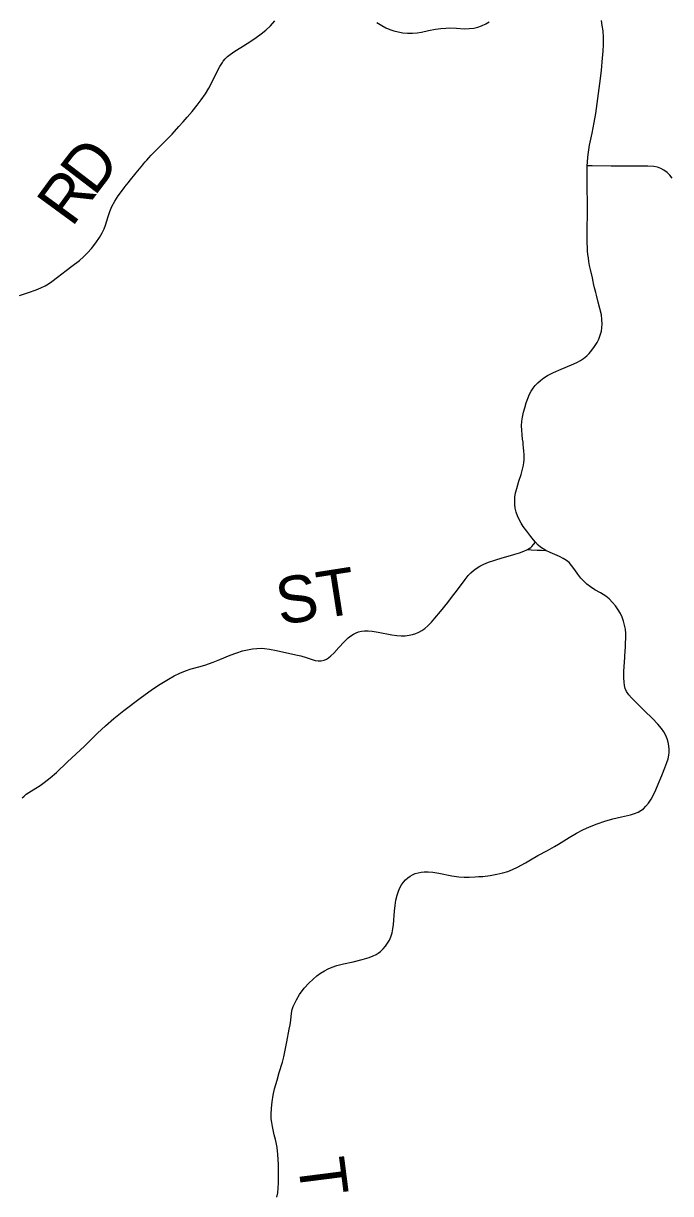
# Model space of a CAD drawing. Extents: x 0 to 34, y 0 to 22.
# Drawn here: x 5.245 to 6.032, y 14.51 to 15.933 of the extents above; entities that cross this region are included whole.
import ezdxf

# ---------------------------------------------------------------- set-up
doc = ezdxf.new("R2010")
doc.units = 0
doc.layers.add('GM_X_Township_Road', color=7, linetype='Continuous')
doc.layers.add('GM_X_Township_Road_Text', color=7, linetype='Continuous')

msp = doc.modelspace()

# ---------------------------------------------------------------- linework, layer by layer
at = {"layer": 'GM_X_Township_Road'}
for points in [[(5.2404, 15.6019), (5.251, 15.6055), (5.2603, 15.6088), (5.2661, 15.6112), (5.2716, 15.6139), (5.2754, 15.6161), (5.2795, 15.6189), (5.2864, 15.6242), (5.2971, 15.6326), (5.304, 15.6378), (5.313, 15.6445), (5.3182, 15.649), (5.323, 15.6538), (5.3279, 15.6594), (5.3332, 15.6662), (5.3374, 15.6724), (5.3409, 15.6783), (5.3432, 15.6833), (5.3447, 15.6874), (5.3464, 15.6927), (5.348, 15.6981), (5.3499, 15.704), (5.3527, 15.7102), (5.3562, 15.7168), (5.3603, 15.7232), (5.3641, 15.7285), (5.3675, 15.7329), (5.3701, 15.7362), (5.3727, 15.7395), (5.3735, 15.7405), (5.382, 15.7511), (5.3901, 15.7611), (5.391, 15.762), (5.3929, 15.7644), (5.3941, 15.7658), (5.3949, 15.7667), (5.3974, 15.7694), (5.4004, 15.7726), (5.417, 15.7893), (5.4257, 15.7983), (5.434, 15.8074), (5.4394, 15.8134), (5.4442, 15.819), (5.4502, 15.826), (5.4564, 15.8335), (5.4612, 15.8398), (5.4663, 15.8474), (5.4703, 15.8541), (5.4758, 15.8643), (5.4812, 15.8753), (5.484, 15.8807), (5.4869, 15.8852), (5.488, 15.887), (5.4903, 15.8898), (5.493, 15.8925), (5.4963, 15.8952), (5.5019, 15.8992), (5.5093, 15.9038), (5.5204, 15.9106), (5.5282, 15.9157), (5.5342, 15.9201), (5.5399, 15.9249), (5.5453, 15.9301), (5.5507, 15.936)], [(5.6749, 15.9339), (5.6807, 15.9303), (5.6857, 15.9277), (5.6908, 15.9254), (5.6955, 15.9238), (5.7009, 15.9225), (5.7064, 15.9216), (5.712, 15.9211), (5.7182, 15.9211), (5.7238, 15.9216), (5.7293, 15.9224), (5.7378, 15.9242), (5.7463, 15.926), (5.7525, 15.9269), (5.7587, 15.9273), (5.7636, 15.9274), (5.7717, 15.927), (5.781, 15.9265), (5.7872, 15.9266), (5.7928, 15.9272), (5.7976, 15.9282), (5.8022, 15.9299), (5.8074, 15.9323), (5.8114, 15.9349)], [(5.9308, 15.7596), (5.9309, 15.7641), (5.9313, 15.7703), (5.9321, 15.7764), (5.9335, 15.785), (5.9365, 15.7996), (5.9393, 15.8123), (5.9412, 15.8233), (5.946, 15.8597), (5.9479, 15.8757), (5.9494, 15.8912), (5.95, 15.8986), (5.9504, 15.9078), (5.9503, 15.9158), (5.9499, 15.9238), (5.949, 15.9304), (5.9479, 15.9365)], [(5.8678, 15.302), (5.8652, 15.3051), (5.8621, 15.309), (5.8571, 15.3155), (5.8528, 15.3212), (5.8503, 15.3252), (5.8478, 15.3295), (5.8458, 15.334), (5.8442, 15.3387), (5.8431, 15.3435), (5.8426, 15.3478), (5.8425, 15.3521), (5.8428, 15.357), (5.8436, 15.3619), (5.845, 15.3673), (5.8477, 15.3762), (5.8504, 15.3845), (5.8525, 15.3923), (5.8532, 15.3959), (5.8537, 15.3989), (5.8539, 15.402), (5.854, 15.4082), (5.8535, 15.4131), (5.8532, 15.417), (5.8528, 15.4209), (5.8526, 15.4237), (5.8521, 15.4274), (5.8516, 15.4328), (5.8511, 15.4382), (5.8509, 15.4436), (5.8513, 15.4493), (5.8521, 15.4541), (5.8532, 15.4603), (5.8547, 15.4656), (5.8564, 15.4714), (5.8583, 15.4768), (5.8605, 15.4819), (5.8625, 15.4858), (5.8648, 15.4894), (5.8675, 15.4928), (5.8705, 15.496), (5.8738, 15.4988), (5.8778, 15.5018), (5.8825, 15.5047), (5.8897, 15.5083), (5.8988, 15.5124), (5.9114, 15.5176), (5.9182, 15.5207), (5.9225, 15.5231), (5.9262, 15.5256), (5.93, 15.5287), (5.9331, 15.5317), (5.9364, 15.5355), (5.9397, 15.54), (5.9426, 15.5447), (5.9448, 15.5491), (5.9466, 15.5538), (5.9479, 15.5586), (5.9485, 15.5629), (5.9487, 15.5678), (5.9485, 15.5728), (5.9479, 15.5784), (5.9461, 15.5864), (5.9441, 15.594), (5.9418, 15.6023), (5.941, 15.6059), (5.9396, 15.6114), (5.9385, 15.6168), (5.9379, 15.6192), (5.9369, 15.6235), (5.9345, 15.6338), (5.9336, 15.6386), (5.9328, 15.6436), (5.9321, 15.6479), (5.9316, 15.6518), (5.9312, 15.6563), (5.9311, 15.66), (5.9308, 15.6659), (5.9305, 15.6708), (5.9306, 15.6745), (5.9306, 15.6801), (5.9307, 15.6838), (5.9307, 15.6868), (5.9308, 15.6899), (5.9309, 15.6948), (5.9309, 15.6991), (5.9309, 15.7066), (5.9309, 15.7129), (5.9309, 15.7203), (5.9307, 15.7271), (5.9305, 15.7362), (5.9305, 15.7461), (5.9307, 15.7559), (5.9308, 15.7596)], [(6.0341, 15.7446), (6.0311, 15.7485), (6.028, 15.7516), (6.024, 15.7545), (6.0202, 15.7565), (6.0161, 15.758), (6.0118, 15.7589), (6.0044, 15.7594), (5.9833, 15.7592), (5.9597, 15.7594), (5.9367, 15.7596), (5.9308, 15.7596)], [(5.8581, 15.2932), (5.8599, 15.2942), (5.8619, 15.2956), (5.8632, 15.2969), (5.8653, 15.2993), (5.8678, 15.302)], [(5.8804, 15.292), (5.877, 15.2939), (5.874, 15.2961), (5.8712, 15.2984), (5.8678, 15.302)], [(5.2435, 14.9911), (5.2457, 14.9933), (5.2485, 14.9957), (5.2516, 14.9978), (5.2602, 15.0028), (5.2653, 15.0062), (5.2703, 15.0099), (5.2776, 15.0157), (5.2851, 15.0222), (5.2983, 15.0344), (5.3195, 15.0545), (5.335, 15.0698), (5.3446, 15.0787), (5.355, 15.0875), (5.3671, 15.0972), (5.387, 15.1122), (5.402, 15.1232), (5.4113, 15.1294), (5.4213, 15.1356), (5.4284, 15.1395), (5.4351, 15.1427), (5.442, 15.1455), (5.449, 15.1479), (5.4598, 15.151), (5.4669, 15.1531), (5.4699, 15.154), (5.4757, 15.1562), (5.4838, 15.1594), (5.4964, 15.1647), (5.5045, 15.1677), (5.5116, 15.1699), (5.5175, 15.1713), (5.5235, 15.1724), (5.529, 15.1729), (5.5345, 15.1731), (5.5381, 15.1729), (5.5442, 15.172), (5.5526, 15.1703), (5.5762, 15.1651), (5.5822, 15.1638), (5.5887, 15.1618), (5.5963, 15.1593), (5.5998, 15.1584), (5.6035, 15.1578), (5.6071, 15.1577), (5.6106, 15.1586), (5.6134, 15.1599), (5.616, 15.1615), (5.6188, 15.1638), (5.6224, 15.1672), (5.6287, 15.174), (5.635, 15.1808), (5.6398, 15.1856), (5.6432, 15.1884), (5.6463, 15.1904), (5.6496, 15.192), (5.6526, 15.193), (5.6562, 15.1939), (5.6599, 15.1943), (5.6642, 15.1944), (5.6691, 15.1939), (5.6764, 15.1927), (5.6932, 15.1893), (5.6993, 15.1885), (5.7042, 15.1882), (5.7091, 15.1882), (5.714, 15.1889), (5.7183, 15.1898), (5.7224, 15.1912), (5.7258, 15.1927), (5.7296, 15.1948), (5.7332, 15.1973), (5.737, 15.2004), (5.7414, 15.2048), (5.7455, 15.2095), (5.7522, 15.2176), (5.7611, 15.2287), (5.7682, 15.238), (5.7704, 15.2409), (5.7821, 15.2569), (5.786, 15.2617), (5.789, 15.2648), (5.7923, 15.2677), (5.7958, 15.2702), (5.8, 15.2728), (5.805, 15.2753), (5.8107, 15.2777), (5.8183, 15.2804), (5.8272, 15.2831), (5.8403, 15.2867), (5.8426, 15.2875), (5.8485, 15.2893), (5.8537, 15.2912), (5.8572, 15.2927), (5.8581, 15.2932)], [(5.7984, 14.8954), (5.8036, 14.8956), (5.8125, 14.8968), (5.8208, 14.8982), (5.8281, 14.8999), (5.834, 14.9018), (5.8397, 14.904), (5.8459, 14.907), (5.8557, 14.9123), (5.8617, 14.9157), (5.8708, 14.921), (5.8822, 14.9273), (5.8908, 14.9322), (5.8956, 14.935), (5.9087, 14.9431), (5.9178, 14.9483), (5.9255, 14.9522), (5.9334, 14.9558), (5.9426, 14.9595), (5.952, 14.9628), (5.962, 14.9658), (5.9725, 14.9682), (5.9833, 14.9706), (5.9882, 14.972), (5.9927, 14.9739), (5.996, 14.9757), (5.999, 14.9779), (6.002, 14.9809), (6.0052, 14.9848), (6.0084, 14.9894), (6.0105, 14.9932), (6.014, 15.0011), (6.0168, 15.008), (6.0214, 15.0182), (6.0252, 15.0278), (6.0276, 15.0343), (6.029, 15.0385), (6.03, 15.043), (6.0304, 15.0464), (6.0304, 15.0501), (6.03, 15.0544), (6.0292, 15.0587), (6.028, 15.0629), (6.0263, 15.0669), (6.024, 15.0713), (6.0211, 15.0755), (6.0166, 15.0806), (6.0101, 15.0875), (6.0004, 15.0971), (5.9903, 15.1072), (5.9846, 15.1128), (5.9812, 15.1166), (5.9785, 15.1205), (5.9768, 15.1241), (5.9759, 15.128), (5.9756, 15.1318), (5.9752, 15.1373), (5.9754, 15.1448), (5.9764, 15.1624), (5.9769, 15.1706), (5.9771, 15.1737), (5.9774, 15.1793), (5.9776, 15.1853), (5.9776, 15.191), (5.9771, 15.1965), (5.9762, 15.2013), (5.9749, 15.206), (5.9732, 15.2107), (5.9711, 15.2152), (5.9683, 15.22), (5.9651, 15.2246), (5.9615, 15.2289), (5.9572, 15.2333), (5.9533, 15.2365), (5.947, 15.2404), (5.94, 15.2442), (5.9345, 15.2476), (5.9302, 15.251), (5.9263, 15.2549), (5.923, 15.2584), (5.9193, 15.2632), (5.9155, 15.2686), (5.9117, 15.2739), (5.9086, 15.2774), (5.9054, 15.28), (5.9015, 15.2823), (5.8968, 15.2845), (5.8858, 15.2894), (5.8804, 15.292)], [(5.8581, 15.2932), (5.8627, 15.2929), (5.8699, 15.2924), (5.8749, 15.2922), (5.8804, 15.292)], [(5.5532, 14.5056), (5.5542, 14.5109), (5.5549, 14.5166), (5.5554, 14.5232), (5.5554, 14.5328), (5.5552, 14.5453), (5.5544, 14.5575), (5.5534, 14.5659), (5.5525, 14.572), (5.5517, 14.5758), (5.5501, 14.5816), (5.5478, 14.5915), (5.5469, 14.5963), (5.5464, 14.6007), (5.5463, 14.6062), (5.5467, 14.6137), (5.5475, 14.6217), (5.5488, 14.6297), (5.5505, 14.6375), (5.5534, 14.6477), (5.5562, 14.6572), (5.5599, 14.6697), (5.5615, 14.6763), (5.5654, 14.6946), (5.5683, 14.7098), (5.5693, 14.7153), (5.5701, 14.7209), (5.5711, 14.7295), (5.572, 14.7338), (5.5732, 14.7373), (5.5747, 14.7407), (5.577, 14.7457), (5.5807, 14.7521), (5.5864, 14.7596), (5.592, 14.7657), (5.5973, 14.7707), (5.602, 14.7748), (5.6064, 14.7781), (5.611, 14.781), (5.6155, 14.7832), (5.6206, 14.7854), (5.6263, 14.7873), (5.6341, 14.7894), (5.6461, 14.7918), (5.6569, 14.7946), (5.6653, 14.7971), (5.6705, 14.799), (5.6738, 14.8006), (5.6765, 14.8023), (5.6794, 14.8045), (5.6826, 14.8075), (5.6854, 14.8109), (5.6878, 14.8144), (5.69, 14.8182), (5.6917, 14.8222), (5.6933, 14.8269), (5.6944, 14.8318), (5.6952, 14.8373), (5.6962, 14.8534), (5.6969, 14.8602), (5.6981, 14.8669), (5.6995, 14.8729), (5.7011, 14.8777), (5.7028, 14.8816), (5.7049, 14.8854), (5.7071, 14.8885), (5.7095, 14.8913), (5.7123, 14.8938), (5.7153, 14.896), (5.718, 14.8976), (5.7214, 14.8991), (5.7249, 14.9002), (5.7286, 14.9009), (5.7323, 14.9013), (5.7373, 14.9013), (5.7428, 14.9008), (5.7502, 14.8996), (5.766, 14.8962), (5.7746, 14.8951), (5.781, 14.8948), (5.787, 14.8948), (5.7943, 14.8951), (5.7984, 14.8954)]]:
    msp.add_lwpolyline(points, dxfattribs=at)

# ---------------------------------------------------------------- texts
at = {"layer": 'GM_X_Township_Road_Text'}
for s, height, rotation, p in [('D', 0.0568, 52.5822, (5.3312, 15.7214)), ('R', 0.0568, 53.8162, (5.3039, 15.6839)), ('ST', 0.05682, 8.8802, (5.5568, 15.2012)), ('T', 0.0568, 277.2664, (5.5784, 14.5499))]:
    msp.add_text(s, height=height, rotation=rotation, dxfattribs=at).set_placement(p)

doc.saveas('drawing.dxf')
